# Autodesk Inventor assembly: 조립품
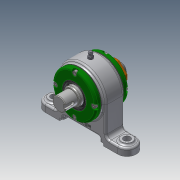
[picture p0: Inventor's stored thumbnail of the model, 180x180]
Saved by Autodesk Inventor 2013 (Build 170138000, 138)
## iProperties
Created: 2019-05
Part Number: 조립품
Document SubType Name: Assembly
Designer: user
Author: user
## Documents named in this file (13)
- C:\Users\user\Desktop\490504V1012\조립품.iam
- C:\Users\user\Desktop\490504V1012\본체.ipt
- C:\Users\user\Desktop\490504V1012\개스킷.ipt
- C:\Users\user\Desktop\490504V1012\그리스니플 M6.ipt
- 그리스니플  M6.ipt
- C:\Users\user\Desktop\490504V1012\그리스니플개스킷.ipt
- C:\Users\user\Desktop\490504V1012\베어링너트.ipt
- C:\Users\user\Desktop\490504V1012\볼트 M4.ipt
- C:\Users\user\Desktop\490504V1012\앵귤러 볼 베어링 7205.ipt
- C:\Users\user\Desktop\490504V1012\오일 실 28 40 5 B.ipt
- C:\Users\user\Desktop\490504V1012\축.ipt
- C:\Users\user\Desktop\490504V1012\칼라.ipt
- C:\Users\user\Desktop\490504V1012\커버.ipt
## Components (4 placed, 3 different names)
1. 개스킷:1
2. 그리스니플  M6:1
3. 그리스니플개스킷:1
4. 개스킷:2
